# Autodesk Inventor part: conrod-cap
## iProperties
Created: 2002-08
Part Number: conrod-cap
Document SubType Name: Modeling
Designer: t_munrn
Density: 1 g/cm^3
Control State: 0
Master: False
Checked Out: False
Shininess: 64.0
Length Units: 11269
Angle Units: 11279
Time Units: 11290
Mass Units: 11283
Length Display Precision: 3
Angle Display Precision: 2
Density: 0.0
Volumn: 0.0
Area: 0.0
PropertySet Name: Model Information
Author: t_munrn
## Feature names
1. Extrusion1
2. Fillet1
3. Extrusion2
4. Mirror1
5. Extrusion3
6. Hole1
7. Mirror2
8. Fillet6
9. Fillet7
10. Fillet8
11. Fillet9
12. Fillet10
